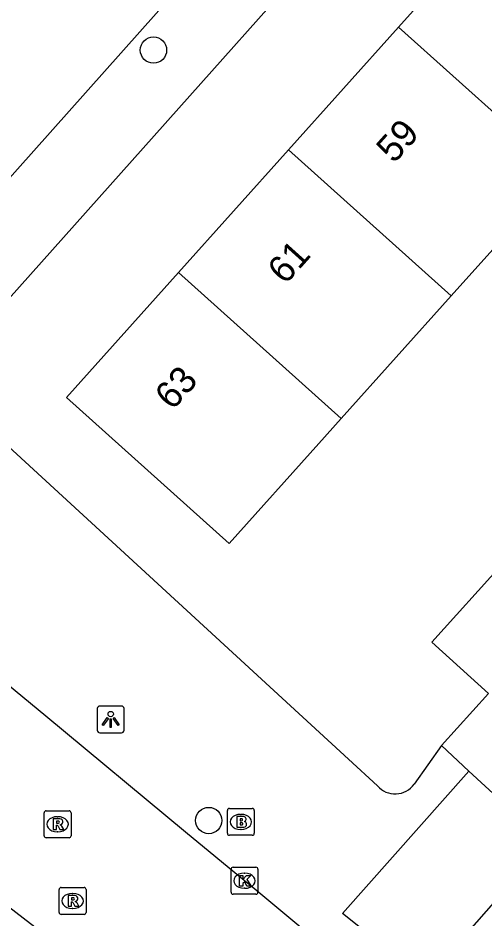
# Model space of a CAD drawing. Extents: x 159040 to 160094, y 381214 to 382518.
# Drawn here: x 159422.45 to 159439.83, y 382003.65 to 382037.16 of the extents above; entities that cross this region are included whole.
import ezdxf

# ---------------------------------------------------------------- set-up
doc = ezdxf.new("R2010")
doc.units = 0
for name, color, linetype in [('IMGEO_Boom', 7, 'Continuous'), ('IMGEO_Brandkraan', 7, 'Continuous'), ('IMGEO_Kolk', 7, 'Continuous'), ('IMGEO_Lichtpunt', 7, 'Continuous'), ('IMGEO_Pand', 7, 'Continuous'), ('IMGEO_Pand_nummerreeks', 7, 'Continuous'), ('IMGEO_Rijbaan_lokaal_open', 7, 'Continuous'), ('IMGEO_Rioolput', 7, 'Continuous'), ('IMGEO_Voetpad_open', 7, 'Continuous')]:
    doc.layers.add(name, color=color, linetype=linetype)

msp = doc.modelspace()

# ---------------------------------------------------------------- linework, layer by layer
at = {"layer": 'IMGEO_Boom'}
for centre in [(159427.491, 382035.97), (159429.548, 382007.316)]:
    msp.add_circle(centre, 0.489, dxfattribs=at)
at = {"layer": 'IMGEO_Brandkraan'}
for p, q in [((159430.315, 382007.766), (159431.167, 382007.766)), ((159430.24, 382006.84), (159430.24, 382007.692)), ((159430.728, 382007.546), (159430.753, 382007.546)), ((159431.241, 382007.692), (159431.241, 382006.84)), ((159431.167, 382006.766), (159430.315, 382006.766)), ((159430.751, 382006.986), (159430.726, 382006.986))]:
    msp.add_line(p, q, dxfattribs=at)
for points in [[(159430.315, 382007.766), (159431.167, 382007.766)], [(159430.24, 382006.84), (159430.24, 382007.692)], [(159430.588, 382007.466), (159430.588, 382007.066), (159430.801, 382007.066)], [(159430.819, 382007.466), (159430.588, 382007.466)], [(159431.241, 382007.692), (159431.241, 382006.84)], [(159430.767, 382007.385), (159430.713, 382007.385), (159430.713, 382007.309)], [(159430.713, 382007.309), (159430.766, 382007.309)], [(159430.775, 382007.233), (159430.713, 382007.233), (159430.713, 382007.152)], [(159430.713, 382007.152), (159430.775, 382007.152)], [(159431.167, 382006.766), (159430.315, 382006.766)]]:
    msp.add_lwpolyline(points, dxfattribs=at)
for centre, radius, start, end in [((159430.317, 382007.69), 0.0765, 91.552, 178.448), ((159430.317, 382007.69), 0.0765, 91.552, 178.448), ((159431.165, 382007.69), 0.0765, 1.552, 88.448), ((159431.165, 382007.69), 0.0765, 1.552, 88.448), ((159430.823, 382007.321), 0.145, 59.4692, 91.5367), ((159430.848, 382007.368), 0.0922, 285.5137, 58.1501), ((159430.768, 382007.347), 0.0379, 267.8285, 90.9355), ((159430.776, 382007.192), 0.0404, 269.8759, 90.5077), ((159430.807, 382007.317), 0.251, 268.6676, 293.5347), ((159430.853, 382007.176), 0.105, 301.3115, 78.989), ((159430.317, 382006.842), 0.0765, 181.552, 268.448), ((159430.317, 382006.842), 0.0765, 181.552, 268.448), ((159431.165, 382006.842), 0.0765, 271.552, 358.448), ((159431.165, 382006.842), 0.0765, 271.552, 358.448)]:
    msp.add_arc(centre, radius, start, end, dxfattribs=at)
for centre, major_axis, ratio, start_param, end_param in [((159430.727, 382007.266), (-0.387, 0.002), 0.722429, 4.712389, 7.853982), ((159430.752, 382007.266), (-0.39, 0.002), 0.717154, 1.570796, 4.712389)]:
    msp.add_ellipse(centre, major_axis=major_axis, ratio=ratio, start_param=start_param, end_param=end_param, dxfattribs=at)
at = {"layer": 'IMGEO_Kolk'}
for p, q in [((159430.377, 382004.65), (159430.377, 382005.502)), ((159430.452, 382005.576), (159431.304, 382005.576)), ((159431.378, 382005.502), (159431.378, 382004.65)), ((159430.865, 382005.356), (159430.89, 382005.356)), ((159430.888, 382004.796), (159430.863, 382004.796)), ((159431.304, 382004.576), (159430.452, 382004.576))]:
    msp.add_line(p, q, dxfattribs=at)
for points in [[(159430.377, 382004.65), (159430.377, 382005.502)], [(159430.452, 382005.576), (159431.304, 382005.576)], [(159431.378, 382005.502), (159431.378, 382004.65)], [(159430.698, 382005.276), (159430.821, 382005.276), (159430.821, 382005.125), (159430.951, 382005.276), (159431.115, 382005.276), (159430.969, 382005.125), (159431.122, 382004.876), (159430.97, 382004.876), (159430.885, 382005.04), (159430.821, 382004.973), (159430.821, 382004.876), (159430.698, 382004.876), (159430.698, 382005.276)], [(159431.304, 382004.576), (159430.452, 382004.576)]]:
    msp.add_lwpolyline(points, dxfattribs=at)
for centre, start, end in [((159430.454, 382005.5), 91.552, 178.448), ((159430.454, 382005.5), 91.552, 178.448), ((159431.302, 382005.5), 1.552, 88.448), ((159431.302, 382005.5), 1.552, 88.448), ((159430.454, 382004.652), 181.552, 268.448), ((159430.454, 382004.652), 181.552, 268.448), ((159431.302, 382004.652), 271.552, 358.448), ((159431.302, 382004.652), 271.552, 358.448)]:
    msp.add_arc(centre, 0.0765, start, end, dxfattribs=at)
for centre, major_axis, ratio, start_param, end_param in [((159430.864, 382005.076), (-0.387, 0.002), 0.722429, 4.712389, 7.853982), ((159430.889, 382005.076), (-0.39, 0.002), 0.717154, 1.570796, 4.712389)]:
    msp.add_ellipse(centre, major_axis=major_axis, ratio=ratio, start_param=start_param, end_param=end_param, dxfattribs=at)
at = {"layer": 'IMGEO_Lichtpunt'}
for p, q in [((159425.4, 382011.479), (159425.4, 382010.672)), ((159425.4, 382011.479), (159425.4, 382010.672)), ((159426.302, 382011.574), (159425.494, 382011.574)), ((159426.302, 382011.574), (159425.494, 382011.574)), ((159426.396, 382010.672), (159426.396, 382011.479)), ((159426.396, 382010.672), (159426.396, 382011.479)), ((159425.494, 382010.578), (159426.302, 382010.578)), ((159425.494, 382010.578), (159426.302, 382010.578))]:
    msp.add_line(p, q, dxfattribs=at)
for points in [[(159425.774, 382011.143), (159425.813, 382011.115), (159425.625, 382010.853), (159425.587, 382010.88), (159425.774, 382011.143)], [(159425.876, 382011.095), (159425.923, 382011.095), (159425.923, 382010.773), (159425.876, 382010.773), (159425.876, 382011.095)], [(159425.986, 382011.115), (159426.024, 382011.142), (159426.211, 382010.88), (159426.172, 382010.852), (159425.986, 382011.115)]]:
    msp.add_lwpolyline(points, dxfattribs=at)
msp.add_circle((159425.899, 382011.277), 0.0994, dxfattribs=at)
for centre, start, end in [((159425.494, 382011.479), 90, 180), ((159425.494, 382011.479), 90, 180), ((159426.302, 382011.479), 0, 90), ((159426.302, 382011.479), 0, 90), ((159425.494, 382010.672), 180, 270), ((159425.494, 382010.672), 180, 270), ((159426.302, 382010.672), 270, 0), ((159426.302, 382010.672), 270, 360)]:
    msp.add_arc(centre, 0.0946, start, end, dxfattribs=at)
at = {"layer": 'IMGEO_Pand'}
for points in [[(159436.609, 382036.825), (159440.704, 382041.387)], [(159432.516, 382032.263), (159436.609, 382036.825)], [(159442.667, 382031.388), (159436.609, 382036.825)], [(159428.421, 382027.701), (159432.516, 382032.263)], [(159438.573, 382026.826), (159432.516, 382032.263)], [(159442.667, 382031.388), (159438.573, 382026.826)], [(159434.479, 382022.264), (159433.647, 382021.337), (159430.307, 382017.615), (159424.249, 382023.052), (159428.421, 382027.701)], [(159428.421, 382027.701), (159434.479, 382022.264)], [(159438.573, 382026.826), (159434.479, 382022.264)], [(159439.956, 382012.046), (159437.85, 382013.944), (159440.488, 382016.871)]]:
    msp.add_lwpolyline(points, dxfattribs=at)
at = {"layer": 'IMGEO_Rijbaan_lokaal_open'}
for points in [[(159417.471, 382026.041), (159418.427, 382027.145), (159421.101, 382030.063), (159436.695, 382047.561), (159444.758, 382056.431), (159447.825, 382059.867), (159456.22, 382069.32), (159461.578, 382075.157), (159466.546, 382080.765), (159473.262, 382088.194), (159486.13, 382102.405), (159490.537, 382107.476)], [(159493.902, 381953.566), (159490.011, 381956.729), (159478.439, 381966.173), (159470.716, 381972.439), (159465.366, 381976.894), (159453.588, 381986.5), (159445.068, 381993.5), (159438.342, 381999.131), (159437.228, 382000), (159436.96, 382000.209), (159433.343, 382003.032), (159431.111, 382004.883), (159430.938, 382005.027), (159428.686, 382006.888), (159423.484, 382011.193), (159418.831, 382015.025), (159418.213, 382015.458)], [(159439.956, 382012.046), (159438.213, 382010.111)], [(159438.213, 382010.111), (159439.224, 382009.155)], [(159414.649, 382009.857), (159428.781, 381998.963)], [(159442.11, 382006.504), (159437.623, 382001.389), (159434.521, 382003.863), (159439.224, 382009.155)], [(159439.224, 382009.155), (159442.11, 382006.504)]]:
    msp.add_lwpolyline(points, dxfattribs=at)
at = {"layer": 'IMGEO_Rioolput'}
for p, q in [((159423.422, 382006.752), (159423.422, 382007.604)), ((159423.497, 382007.678), (159424.349, 382007.678)), ((159423.91, 382007.458), (159423.935, 382007.458)), ((159424.423, 382007.604), (159424.423, 382006.752)), ((159423.933, 382006.898), (159423.908, 382006.898)), ((159424.349, 382006.678), (159423.497, 382006.678)), ((159423.981, 382003.899), (159423.981, 382004.751)), ((159424.056, 382004.825), (159424.908, 382004.825)), ((159424.982, 382004.751), (159424.982, 382003.899)), ((159424.469, 382004.605), (159424.494, 382004.605)), ((159424.908, 382003.825), (159424.056, 382003.825)), ((159424.492, 382004.045), (159424.467, 382004.045))]:
    msp.add_line(p, q, dxfattribs=at)
for points in [[(159423.422, 382006.752), (159423.422, 382007.604)], [(159423.497, 382007.678), (159424.349, 382007.678)], [(159424.423, 382007.604), (159424.423, 382006.752)], [(159424.011, 382007.376), (159423.759, 382007.378), (159423.759, 382006.978)], [(159423.759, 382006.978), (159423.883, 382006.978), (159423.883, 382007.14), (159423.894, 382007.14)], [(159423.937, 382007.297), (159423.883, 382007.297), (159423.883, 382007.216)], [(159423.883, 382007.216), (159423.935, 382007.216)], [(159423.941, 382007.111), (159424.012, 382006.978), (159424.152, 382006.978), (159424.087, 382007.104)], [(159424.349, 382006.678), (159423.497, 382006.678)], [(159423.981, 382003.899), (159423.981, 382004.751)], [(159424.056, 382004.825), (159424.908, 382004.825)], [(159424.982, 382004.751), (159424.982, 382003.899)], [(159424.57, 382004.523), (159424.318, 382004.525), (159424.318, 382004.125)], [(159424.496, 382004.444), (159424.442, 382004.444), (159424.442, 382004.363)], [(159424.318, 382004.125), (159424.442, 382004.125), (159424.442, 382004.287), (159424.453, 382004.287)], [(159424.442, 382004.363), (159424.494, 382004.363)], [(159424.5, 382004.258), (159424.571, 382004.125), (159424.711, 382004.125), (159424.646, 382004.251)], [(159424.908, 382003.825), (159424.056, 382003.825)]]:
    msp.add_lwpolyline(points, dxfattribs=at)
for centre, radius, start, end in [((159423.499, 382007.602), 0.0765, 91.552, 178.448), ((159423.499, 382007.602), 0.0765, 91.552, 178.448), ((159424.347, 382007.602), 0.0765, 1.552, 88.448), ((159424.347, 382007.602), 0.0765, 1.552, 88.448), ((159423.893, 382007.087), 0.0533, 26.0293, 88.6989), ((159423.919, 382007.405), 0.19, 274.7715, 282.9687), ((159423.943, 382007.201), 0.0964, 77.0061, 93.1865), ((159423.957, 382007.258), 0.0378, 276.6634, 79.6772), ((159424.01, 382007.266), 0.109, 350.3612, 89.416), ((159424.008, 382007.266), 0.112, 277.5842, 350.9817), ((159423.992, 382007.051), 0.108, 29.5134, 73.7905), ((159423.499, 382006.754), 0.0765, 181.552, 268.448), ((159423.499, 382006.754), 0.0765, 181.552, 268.448), ((159424.347, 382006.754), 0.0765, 271.552, 358.448), ((159424.347, 382006.754), 0.0765, 271.552, 358.448), ((159424.058, 382004.749), 0.0765, 91.552, 178.448), ((159424.058, 382004.749), 0.0765, 91.552, 178.448), ((159424.906, 382004.749), 0.0765, 1.552, 88.448), ((159424.906, 382004.749), 0.0765, 1.552, 88.448), ((159424.502, 382004.348), 0.0964, 77.0061, 93.1865), ((159424.516, 382004.405), 0.0378, 276.6634, 79.6772), ((159424.569, 382004.413), 0.109, 350.3612, 89.416), ((159424.567, 382004.413), 0.112, 277.5842, 350.9817), ((159424.452, 382004.234), 0.0533, 26.0293, 88.6989), ((159424.478, 382004.552), 0.19, 274.7715, 282.9687), ((159424.551, 382004.198), 0.108, 29.5134, 73.7905), ((159424.058, 382003.901), 0.0765, 181.552, 268.448), ((159424.058, 382003.901), 0.0765, 181.552, 268.448), ((159424.906, 382003.901), 0.0765, 271.552, 358.448), ((159424.906, 382003.901), 0.0765, 271.552, 358.448)]:
    msp.add_arc(centre, radius, start, end, dxfattribs=at)
for centre, major_axis, ratio, start_param, end_param in [((159423.909, 382007.178), (-0.387, 0.002), 0.722429, 4.712389, 7.853982), ((159423.934, 382007.178), (-0.39, 0.002), 0.717154, 1.570796, 4.712389), ((159424.468, 382004.325), (-0.387, 0.002), 0.722429, 4.712389, 7.853982), ((159424.493, 382004.325), (-0.39, 0.002), 0.717154, 1.570796, 4.712389)]:
    msp.add_ellipse(centre, major_axis=major_axis, ratio=ratio, start_param=start_param, end_param=end_param, dxfattribs=at)
at = {"layer": 'IMGEO_Voetpad_open'}
for points in [[(159420.759, 382025.224), (159440.696, 382047.571), (159445.905, 382053.353)], [(159435.825, 382008.602), (159434.747, 382009.592), (159420.547, 382022.636)], [(159438.213, 382010.111), (159437.186, 382008.666)]]:
    msp.add_lwpolyline(points, dxfattribs=at)
msp.add_arc((159436.48, 382009.181), 0.874, 221.4968, 323.8878, dxfattribs=at)

# ---------------------------------------------------------------- texts
at = {"layer": 'IMGEO_Pand_nummerreeks'}
for s, p in [('59', (159436.44, 382031.724)), ('61', (159432.395, 382027.217)), ('63', (159428.199, 382022.542))]:
    msp.add_text(s, height=1, rotation=48.0936, dxfattribs=at).set_placement(p)

doc.saveas('drawing.dxf')
